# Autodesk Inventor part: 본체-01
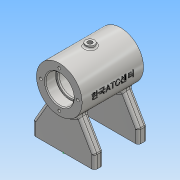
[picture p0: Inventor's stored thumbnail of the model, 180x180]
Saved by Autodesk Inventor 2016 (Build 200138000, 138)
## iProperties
Created: 2018-05
Part Number: 본체-01
Material: 알루미늄 6061
Document SubType Name: Modeling
Designer: Administrator
Density: 2.7 g/cm^3
Appearance: 알루미늄 - 평지
Mass: 319.522 g
Surface Area: 367.57 cm^2
Volume: 118.341 cm^3
Author: Administrator
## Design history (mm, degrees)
sketch "스케치1"
  geometry: L1 (-35, -20)-(35, -20); L2 (35, 20)-(-35, 20); L3 (-35, -20)-(35, 20); L4 (35, -20)-(-35, 20); L5 (-35, -20)-(-35, -30); L6 (-35, -30)-(35, -30); L7 (35, -30)-(35, -20); L8 (-35, 20)-(-35, 30); L9 (-35, 30)-(35, 30); L10 (35, 30)-(35, 20); 1 further point
  constraints: 20 end point, 4 perpendicular, 2 midpoint, 2 point on line, 1 horizontal, 1 parallel, 1 vertical
  dimensions: "d0" = 70 distance of L2.end L2.start; "d1" = 40 distance of L2.start L1.end; "d2" = 10 distance of L1.start L5.end; "d3" = 10 distance of L2.end L8.end
extrude "돌출1" new body sketch "스케치1" distance "d4" = 15; taper "d5" = 0 deg
sketch "스케치2"
  geometry: 1 further point
sketch "스케치3"
  geometry: L1 (0, -15)-(70, -15) reference; L2 (70, -15)-(35, -75.622); L3 (70, -15)-(130.842, -15); L4 (0, 0)-(0, -15) reference; L5 (0, -15)-(35, -75.622); L6 (0, -15)-(76.56, -15); 1 further point
  constraints: 8 end point, 2 horizontal
  dimensions: "d6" = 120 deg angle of L2 L3; "d7" = 60 deg angle of L5 L6
extrude "돌출2" join sketch "스케치3" distance "d8" = 10; taper "d9" = 0 deg
sketch "스케치4"
  geometry: L1 (0, 0)-(0, 15) reference; L2 (0, 15)-(35, 75.622); L3 (70, 15)-(35, 75.622) reference; L4 (35, 75.622)-(70, 15); L5 (70, 15)-(0, 15); 1 further point
  constraints: 6 end point, 1 collinear, 1 perpendicular
extrude "돌출3" join sketch "스케치4" distance "d10" = 10; taper "d11" = 0 deg
sketch "스케치5"
  geometry: L1 (-30, 75.622)-(-30, 15) reference; L2 (30, 15)-(30, 75.622) reference; L3 (-35, 65)-(35, 65); L4 (0, 0)-(0, 65); L5 (-35, 65)-(-35, 91); L6 (-35, 91)-(35, 91); L7 (35, 91)-(35, 65)
  constraints: 10 end point, 2 horizontal, 2 vertical, 1 midpoint, 1 perpendicular
  dimensions: "d12" = 70 distance of L3.start L3.end; "d13" = 65 distance of L4.end L4.start; "d15" = 52 diameter of L6 L3
revolve "회전1" sketch "스케치5" stored, may be unused: angle "d16" = 90 deg
sketch "스케치6"
  geometry: L1 (0, 0)-(0, 65); L2 (-35, 65)-(35, 65); L3 (-35, 65)-(-35, 81); L4 (-35, 39)-(-35, 91) reference; L5 (-35, 81)-(-23, 81); L6 (-23, 81)-(-23, 79); L7 (-23, 79)-(-21, 79); L8 (-21, 79)-(-21, 86); L9 (-21, 86)-(21, 86); L10 (21, 86)-(21, 79); L11 (21, 79)-(23, 79); L12 (23, 79)-(23, 81); L13 (23, 81)-(35, 81); L14 (35, 81)-(35, 65); L15 (35, 39)-(35, 91) reference
  constraints: 26 end point, 6 perpendicular, 5 point on line, 2 horizontal, 1 collinear, 1 midpoint, 1 vertical
  dimensions: "d17" = 65 distance of L1.end L1.start; "d18" = 70 distance of L2.start L2.end; "d19" = 32 diameter of L5 L2; "d20" = 28 diameter of L7 L2; "d21" = 42 diameter of L9 L2; "d22" = 12 distance of L3.end L5.end; "d23" = 2 distance of L6.end L7.end; "d24" = 2 distance of L10.end L11.end; "d25" = 12 distance of L12.end L13.end
revolve "회전2" sketch "스케치6" stored, may be unused: angle "d26" = 90 deg
node "작업 평면1"
sketch "스케치7"
  geometry: C1 r 5 at (0, 0); 1 further point
  constraints: 1 centre point, 1 coincident
  dimensions: "d28" = 10 diameter of C1
extrude "돌출4" join sketch "스케치7" stored distance "d29" = 10; taper "d30" = 0 deg
sketch "스케치8"
  geometry: L1 (0, 0)-(0, -25); L2 (0, -25)-(20, -25); L3 (20, -25)-(20, 25); L4 (20, 25)-(-20, 25); L5 (-20, 25)-(-20, -25); L6 (-20, -25)-(0, -25); 4 further points
  constraints: 12 end point, 4 coincident, 4 perpendicular, 1 point on line, 1 vertical
  dimensions: "d34" = 25 distance of L1.start L1.end; "d35" = 20 distance of L1.end L2.end; "d36" = 50 distance of L2.end L3.end; "d37" = 40 distance of L3.end L4.end; "d38" = 50 distance of L4.end L5.end; "d39" = 20 distance of L5.end L1.end (derived)
hole "구멍1" sketch "스케치8" at (-20, -25), (20, -25), (20, 25), (-20, 25) diameter "d40" = 4.134; stored, may be unused: countersink angle "d44" = 90 deg, drill point angle "d46" = 118 deg; dims "d41" = 8, "d42" = 4, "d43" = 2, "d45" = 10
hole "구멍2" diameter "d49" = 5.188; stored, may be unused: countersink angle "d53" = 90 deg, drill point angle "d55" = 0 deg; dims "d47" = 10, "d48" = 10, "d50" = 12, "d51" = 4, "d52" = 2, "d54" = 16
sketch "스케치9"
  geometry: L1 (0, 65)-(9.919, 37.749); L2 (0, 65)-(29, 65); L3 (15.557, 39.801)-(9.919, 37.749); L4 (14.063, 43.905)-(15.557, 39.801); L5 (8.425, 41.853)-(9.919, 37.749); L6 (8.425, 41.853)-(14.063, 43.905); C1 r 14 at (0, 65) reference; 1 further point
  constraints: 12 end point, 1 collinear, 1 equal length, 1 horizontal, 1 perpendicular
  dimensions: "d56" = 29 distance of L1.end L1.start; "d57" = 70 deg angle of L1 L2; "d59" = 90 deg angle of L3 L1
revolve "회전3" sketch "스케치9" stored, may be unused: angle "d60" = 90 deg
hole "구멍3" diameter "d63" = 5.188; stored, may be unused: countersink angle "d67" = 90 deg, drill point angle "d69" = 0 deg; dims "d61" = 10, "d62" = 10, "d64" = 12, "d65" = 4, "d66" = 2, "d68" = 16
fillet "모깎기1" dims "d70" = 2
fillet "모깎기2" dims "d71" = 2
fillet "모깎기3" dims "d72" = 3
fillet "모깎기4" dims "d73" = 3
chamfer "모따기1" distance "d74" = 1; stored, may be unused: second distance "d75" = 2, angle "d76" = 45 deg
fillet "모깎기6" dims "d78" = 3
fillet "모깎기7" dims "d79" = 0.3
node "작업 평면2"
sketch "스케치12"
  geometry: 3 further points
  constraints: 1 coincident, 2 other
feature "엠보싱1" sketch "스케치12" dims "d6" = 120 deg, "d7" = 60 deg, "d82" = 0.5, "d83" = 0
sketch "스케치13" dims "d84" = 42
  geometry: L1 (0, 0)-(0, 21); 2 further points
  constraints: 2 end point, 1 coincident, 1 vertical, 1 vertical alignment, 2 other
hole "구멍4" sketch "스케치13" at (0, 21) diameter "d85" = 3.242; stored, may be unused: countersink angle "d89" = 90 deg, drill point angle "d91" = 118 deg; dims "d86" = 8, "d87" = 4, "d88" = 2, "d90" = 10
node "솔리드1"
pattern_circular "원형 패턴1" dims angle "d93" = 360 deg
mirror "대칭1"
other parameters: "d27" = 94
